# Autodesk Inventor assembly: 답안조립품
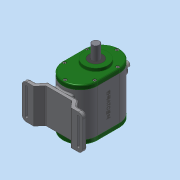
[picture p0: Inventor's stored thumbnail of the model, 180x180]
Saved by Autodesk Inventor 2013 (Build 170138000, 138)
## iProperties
Created: 2018-07
Part Number: 답안조립품
Document SubType Name: Assembly
Designer: dgall
Mass: 2274.38 g
Surface Area: 2005.91 cm^2
Volume: 679.265 cm^3
Density: 3.3483 g/cm^3
Author: dgall
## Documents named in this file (14)
- C:\Users\dgall\Desktop\380707V1007\답안조립품.iam
- C:\Users\dgall\Desktop\380707V1007\본체.ipt
- C:\Users\dgall\Desktop\380707V1007\앞커버.ipt
- C:\Users\dgall\Desktop\380707V1007\베어링 6003.ipt
- C:\Users\dgall\Desktop\380707V1007\베어링 608.ipt
- C:\Users\dgall\Desktop\380707V1007\뒤커버.ipt
- C:\Users\dgall\Desktop\380707V1007\오일 실 17 32 8.ipt
- C:\Users\dgall\Desktop\380707V1007\오일 실 8 22 7.ipt
- C:\Users\dgall\Desktop\380707V1007\서브축.ipt
- C:\Users\dgall\Desktop\380707V1007\메인축.ipt
- C:\Users\dgall\Desktop\380707V1007\부시.ipt
- C:\Users\dgall\Desktop\380707V1007\슬라이더.ipt
- C:\Users\dgall\Desktop\380707V1007\가변스프링.ipt
- C:\Users\dgall\Desktop\380707V1007\볼트 M4.ipt
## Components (1 placed, 1 different names)
1. 가변스프링:1
